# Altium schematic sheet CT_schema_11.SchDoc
size 382 x 278 mm
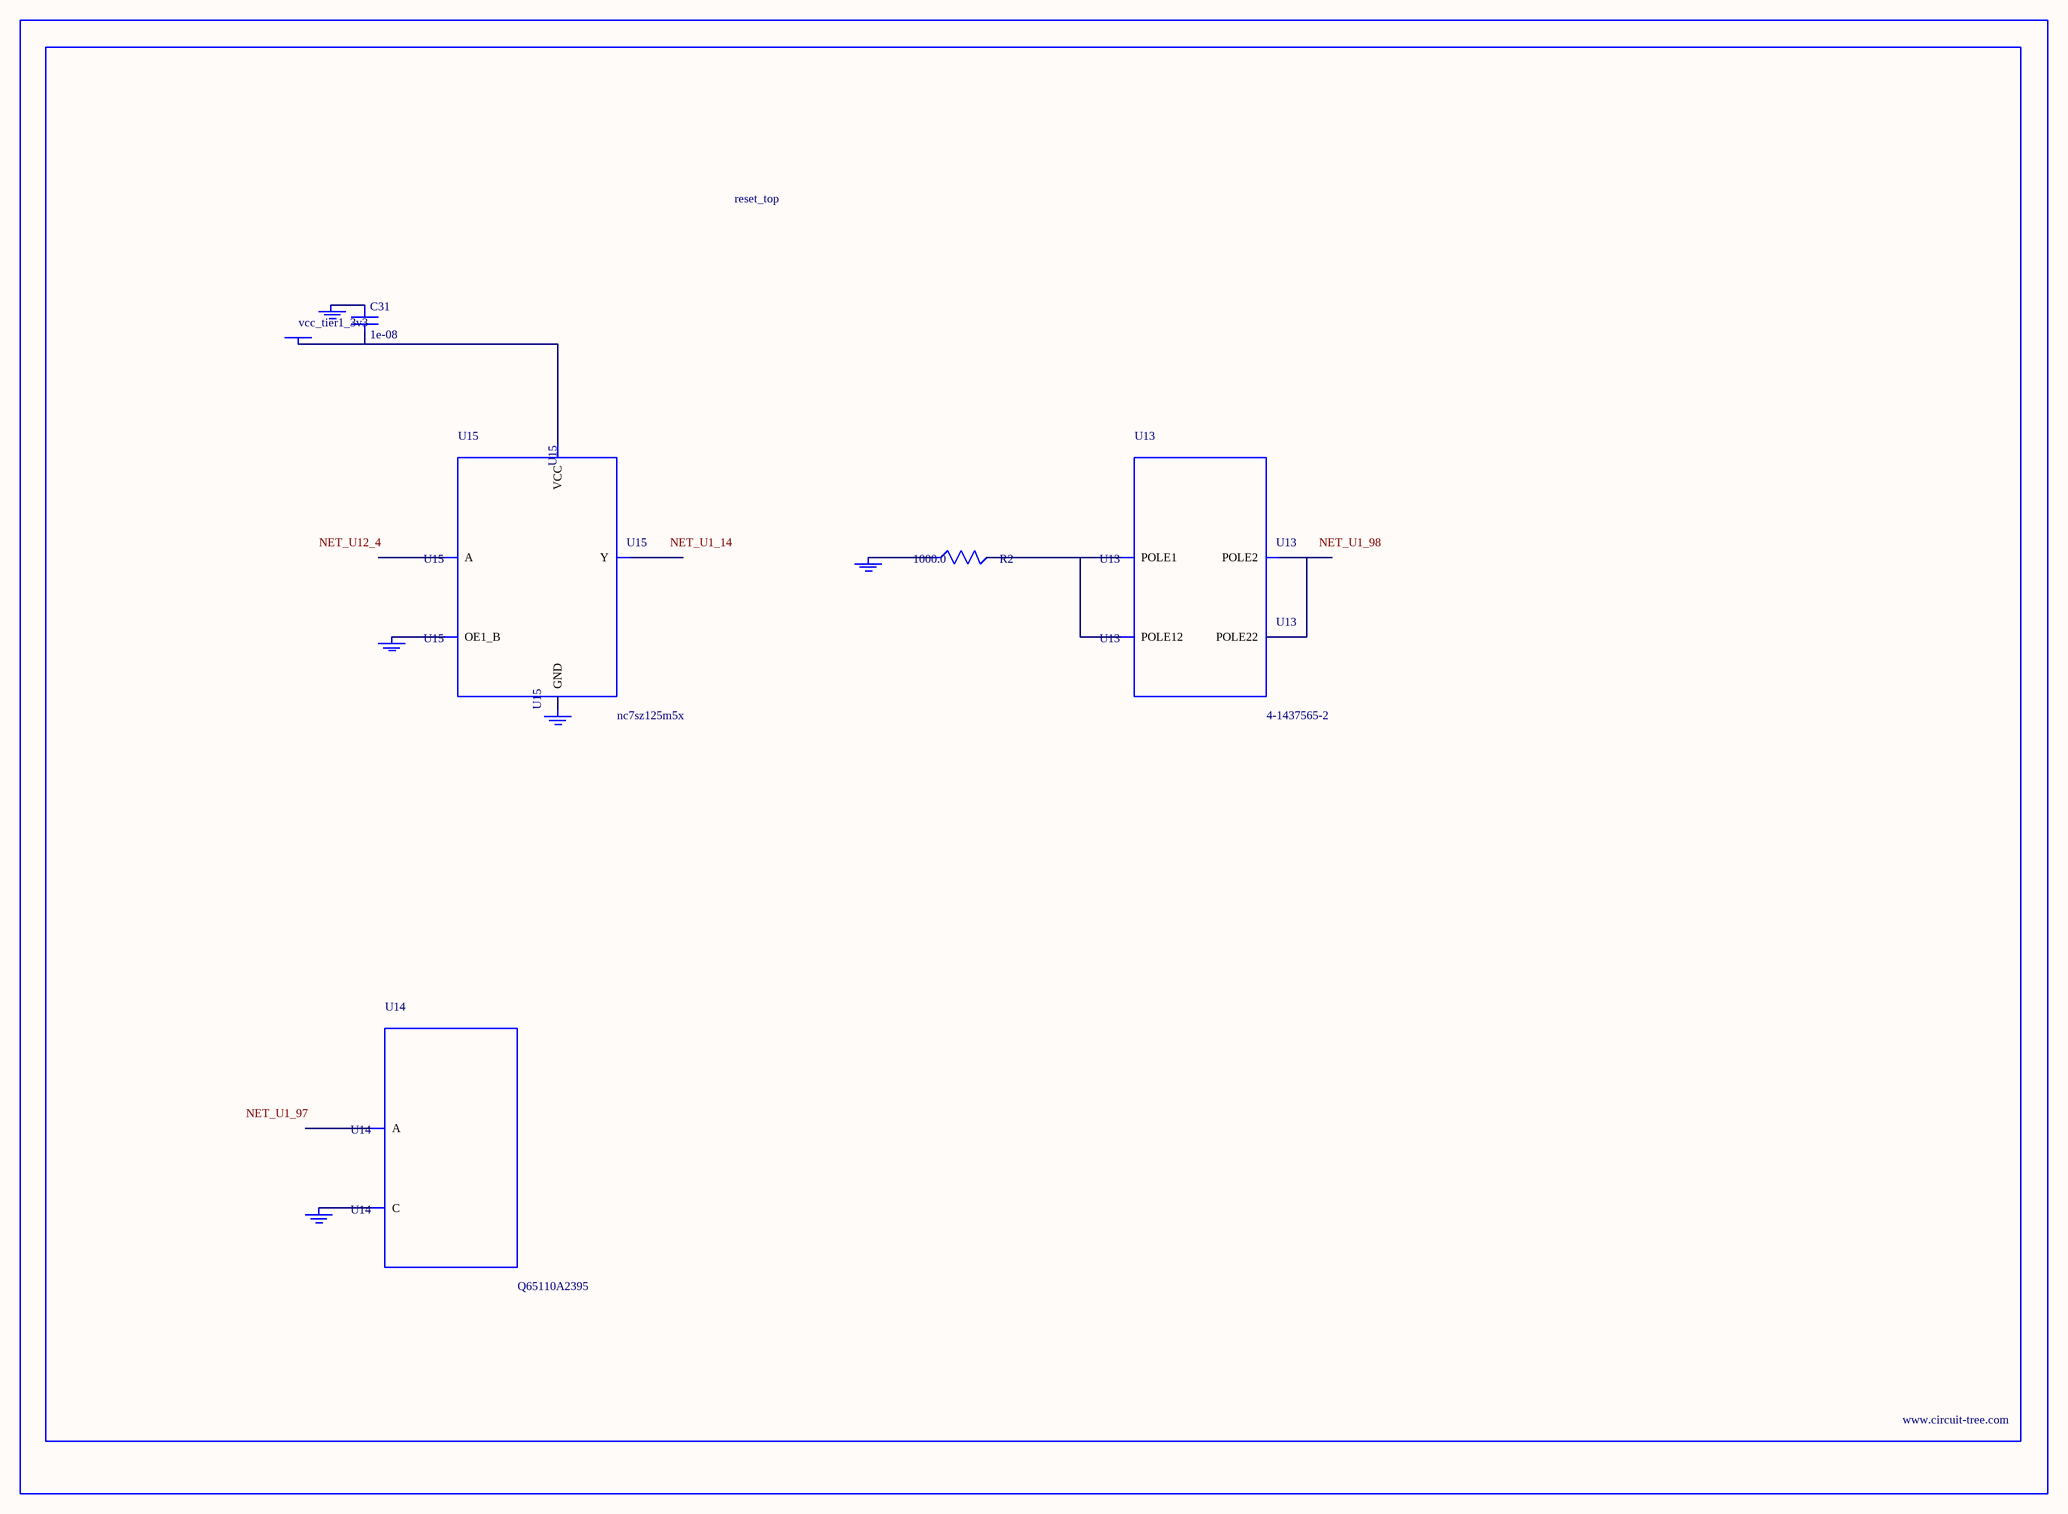
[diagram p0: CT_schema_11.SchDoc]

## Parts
BORDER10  (no value)
C31  1e-08  [C0402]
GND_INSTANCE_10_0  (no value)
GND_INSTANCE_10_1  (no value)
GND_INSTANCE_10_2  (no value)
GND_INSTANCE_10_3  (no value)
GND_INSTANCE_10_4  (no value)
POWER_INSTANCE_10_0  vcc_tier1_3v3
R2  1000.0  [R0603]
U13  4-1437565-2  [SW_4-1437565-2]
U14  Q65110A2395  [LGM67K-G1J2-24-Z]
U15  nc7sz125m5x  [NC7SZ125M5X]

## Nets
NetC31_1: C31.1 GND_INSTANCE_10_2.0(GND)
NetC31_2: C31.2 POWER_INSTANCE_10_0.0(PWR) U15.5(VCC)
NetGND_INSTANCE_10_0_0: GND_INSTANCE_10_0.0(GND) R2.1
NetGND_INSTANCE_10_1_0: GND_INSTANCE_10_1.0(GND) U14.C
NetGND_INSTANCE_10_3_0: GND_INSTANCE_10_3.0(GND) U15.1(OE1_B)
NetGND_INSTANCE_10_4_0: GND_INSTANCE_10_4.0(GND) U15.3(GND)
NetR2_2: R2.2 U13.1(POLE1) U13.2(POLE12)
NetU13_3: U13.3(POLE2) U13.4(POLE22)

Not connected (* = marked no-connect by the designer): U14 A; U15 2(A) 4(Y)

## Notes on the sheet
- Labels drawn without touching a wire or pin: NET_U1_14, NET_U1_97, NET_U1_98, NET_U12_4

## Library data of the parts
BORDER10 = BORDER_PAGE10
C31 = C0402C103K3RAC
GND_INSTANCE_10_0-GND_INSTANCE_10_4 = GND
POWER_INSTANCE_10_0 = PWR
R2 = RC0603JR-071KL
